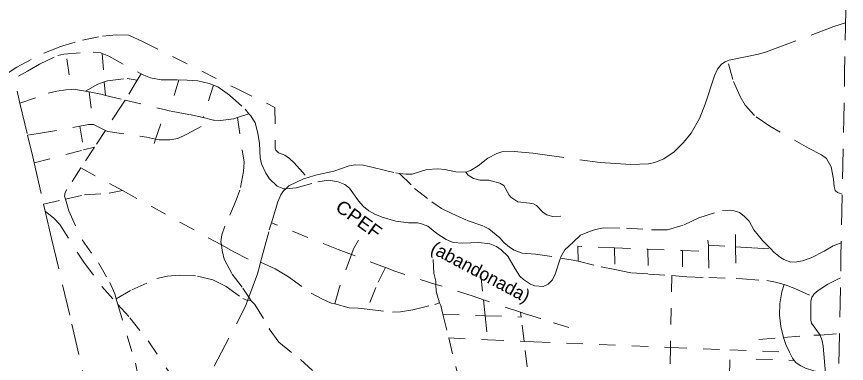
# Model space of a CAD drawing. Extents: x 783.4 to 809.8, y 7536.4 to 7564.6.
# Drawn here: x 804.65 to 809.73, y 7559.21 to 7561.34 of the extents above; entities that cross this region are included whole.
import ezdxf
from ezdxf.enums import TextEntityAlignment as Align

# ---------------------------------------------------------------- set-up
doc = ezdxf.new("R2010")
doc.units = 0
doc.header["$LTSCALE"] = 0.032
for name, pattern in [('DOTTED', [1.5, 0.3, -1.2]), ('LONG_DASHED', [7.5, 6, -1.5]), ('MEDIUM_DASHED', [4.5, 3, -1.5]), ('SHORT_DASHED', [2.7, 1.5, -1.2])]:
    doc.linetypes.add(name, pattern=pattern)
for name, color, linetype, lineweight in [('18', 7, 'DOTTED', 13), ('35', 7, 'SHORT_DASHED', 13), ('5', 7, 'LONG_DASHED', 13), ('6', 7, 'MEDIUM_DASHED', 13), ('7', 7, 'DOTTED', 13)]:
    doc.layers.add(name, color=color, linetype=linetype, lineweight=lineweight)
doc.layers.add('61', color=7, linetype='Continuous')

msp = doc.modelspace()

# ---------------------------------------------------------------- linework, layer by layer
at = {"layer": '18'}
for points in [[(804.1349, 7560.6807), (804.7152, 7561.0021), (804.7883, 7561.0454), (804.9016, 7561.0989), (804.9376, 7561.1074), (805.1165, 7561.1192), (805.1646, 7561.1145), (805.1722, 7561.1112)], [(805.1722, 7561.1112), (805.2127, 7561.0938), (805.4119, 7560.9867)], [(805.4119, 7560.9867), (805.4267, 7560.9787), (805.4678, 7560.9618), (805.5339, 7560.9496), (805.642, 7560.9489)], [(805.642, 7560.9489), (805.6923, 7560.9486), (805.7574, 7560.9439), (805.8271, 7560.9266), (805.8529, 7560.9166)], [(805.8529, 7560.9166), (805.8802, 7560.9059), (805.9524, 7560.8561), (806.0476, 7560.7706), (806.071, 7560.7421)], [(806.071, 7560.7421), (806.0822, 7560.7285), (806.1082, 7560.6871), (806.1252, 7560.6241), (806.1353, 7560.5602), (806.1403, 7560.4728), (806.1473, 7560.4362), (806.1749, 7560.3775), (806.1959, 7560.3436), (806.244, 7560.2985), (806.2851, 7560.2826), (806.2959, 7560.2834)], [(806.2959, 7560.2834), (806.3603, 7560.2882), (806.4925, 7560.3248), (806.5567, 7560.3361), (806.6163, 7560.3262), (806.6574, 7560.3093), (806.6865, 7560.2868), (806.7406, 7560.2097), (806.7717, 7560.1749), (806.8037, 7560.1486), (806.8408, 7560.127), (806.8869, 7560.1092), (806.9701, 7560.0847), (807.0468, 7560.0739), (807.1029, 7560.0739), (807.1279, 7560.0683), (807.166, 7560.0532), (807.2211, 7560.0081), (807.2783, 7559.9724), (807.3204, 7559.9545), (807.3795, 7559.9498), (807.4772, 7559.9531), (807.5444, 7559.9465), (807.5854, 7559.9296), (807.6145, 7559.9089), (807.6556, 7559.8713), (807.6997, 7559.7933), (807.7298, 7559.7482), (807.7509, 7559.7271), (807.7935, 7559.6984), (807.8216, 7559.689), (807.8717, 7559.6853), (807.9017, 7559.6994), (807.9288, 7559.7257), (807.9458, 7559.7595), (807.9777, 7559.8588)], [(807.9777, 7559.8588), (807.9799, 7559.8657), (808.0049, 7559.9099), (808.0547, 7559.9565), (808.0992, 7559.9982), (808.1543, 7560.0217), (808.1919, 7560.0334), (808.241, 7560.0438), (808.3813, 7560.041), (808.5346, 7560.0316), (808.6333, 7560.032), (808.7346, 7560.0611), (808.8248, 7560.1053), (808.9691, 7560.1495), (809.0177, 7560.1509), (809.0408, 7560.1481), (809.0728, 7560.1368), (809.1019, 7560.1152), (809.133, 7560.0842), (809.162, 7560.0325), (809.2151, 7559.9658), (809.2645, 7559.9147)], [(809.2645, 7559.9147), (809.2833, 7559.8953), (809.3254, 7559.8615), (809.3445, 7559.85), (809.3875, 7559.834), (809.4246, 7559.8359), (809.4587, 7559.8424), (809.5118, 7559.8594), (809.592, 7559.9007), (809.6461, 7559.9327), (809.6963, 7559.9524)]]:
    msp.add_lwpolyline(points, dxfattribs=at)
at = {"layer": '35'}
msp.add_lwpolyline([(809.6166, 7555.9048), (809.6222, 7556.1875), (809.6278, 7556.4702), (809.6333, 7556.7528), (809.6389, 7557.0354), (809.6445, 7557.3181), (809.65, 7557.6007), (809.6556, 7557.8834), (809.6612, 7558.166), (809.6667, 7558.4487), (809.6722, 7558.7314), (809.6778, 7559.014), (809.6834, 7559.2967), (809.6889, 7559.5793), (809.6945, 7559.862), (809.7001, 7560.1446), (809.7056, 7560.4272), (809.7112, 7560.7099), (809.7168, 7560.9926), (809.7223, 7561.2752), (809.7278, 7561.5578)], dxfattribs=at)
at = {"layer": '5'}
msp.add_line((804.8138, 7560.188), (804.8235, 7560.1454), dxfattribs=at)
for points in [[(809.0009, 7561.066), (809.0102, 7561.0695), (809.1896, 7561.1071), (809.2387, 7561.1212), (809.6501, 7561.2758), (809.7227, 7561.2979)], [(807.3992, 7560.3855), (807.4278, 7560.3948), (807.4739, 7560.423), (807.533, 7560.4699), (807.5881, 7560.4991), (807.6192, 7560.5085), (807.6943, 7560.5113), (807.8076, 7560.5), (808.22, 7560.4441), (808.4079, 7560.4305), (808.5161, 7560.4361), (808.5542, 7560.4436), (808.6103, 7560.4671), (808.673, 7560.509), (808.7311, 7560.5663), (808.7782, 7560.6236), (808.8283, 7560.7138), (808.8634, 7560.8012), (808.92, 7560.9736), (808.9391, 7561.015), (808.9641, 7561.0451), (808.9852, 7561.0601), (809.0009, 7561.066)], [(804.6518, 7560.8794), (804.669, 7560.8074), (804.7157, 7560.6118)], [(804.7157, 7560.6118), (804.7477, 7560.478), (804.7562, 7560.4409), (804.8138, 7560.188)], [(806.4272, 7560.3506), (806.4772, 7560.3671), (806.5894, 7560.3906), (806.6836, 7560.4234), (806.7217, 7560.43), (806.7718, 7560.4272), (806.9707, 7560.3797), (806.9913, 7560.3772)], [(806.9913, 7560.3772), (807.0329, 7560.3722), (807.0689, 7560.3722), (807.1601, 7560.4004), (807.2273, 7560.4051), (807.2689, 7560.4009), (807.337, 7560.3868), (807.3972, 7560.3849), (807.3992, 7560.3855)], [(806.2959, 7560.2834), (806.3141, 7560.301), (806.4045, 7560.3431), (806.4272, 7560.3506)], [(806.2084, 7560.0741), (806.248, 7560.2023), (806.266, 7560.2465), (806.283, 7560.2709), (806.2959, 7560.2834)], [(804.8235, 7560.1454), (804.8615, 7559.9788), (804.9873, 7559.4549), (805.1943, 7558.5495), (805.2861, 7558.1712), (805.3146, 7558.0338), (805.3268, 7557.9814)], [(806.142, 7559.8336), (806.1953, 7560.0317), (806.2084, 7560.0741)], [(806.0706, 7559.6187), (806.1226, 7559.7616), (806.1368, 7559.8145), (806.142, 7559.8336)], [(809.692, 7559.7376), (809.6148, 7559.6982), (809.5545, 7559.6602), (809.5307, 7559.6394), (809.5193, 7559.6232)], [(805.7227, 7558.9393), (806.0525, 7559.5689), (806.0625, 7559.5988), (806.0706, 7559.6187)], [(809.5193, 7559.6232), (809.5165, 7559.6193), (809.5093, 7559.5918), (809.5093, 7559.4794), (809.5133, 7559.4593), (809.5671, 7559.3876)], [(809.5671, 7559.3876), (809.5803, 7559.3526), (809.5858, 7559.3199), (809.6006, 7559.1539)]]:
    msp.add_lwpolyline(points, dxfattribs=at)
at = {"layer": '6'}
for points in [[(804.5916, 7560.9883), (804.649, 7561.0282), (804.8154, 7561.1128), (804.9116, 7561.1517), (805.0526, 7561.1923), (805.1748, 7561.2174), (805.2594, 7561.2247), (805.3348, 7561.224), (805.4243, 7561.1824), (805.9978, 7560.8938), (806.2298, 7560.7804), (806.2317, 7560.5304), (806.2354, 7560.5199), (806.2517, 7560.5019), (806.2902, 7560.488), (806.3183, 7560.4686), (806.3479, 7560.4409), (806.4272, 7560.3506)], [(809.7021, 7560.2496), (809.6738, 7560.2597), (809.66, 7560.2727), (809.6523, 7560.2958), (809.6492, 7560.342), (809.6344, 7560.4165), (809.6064, 7560.4685), (809.5752, 7560.4909), (809.4968, 7560.5309), (809.2584, 7560.6669), (809.1646, 7560.7323), (809.1091, 7560.7954), (809.0773, 7560.8482), (809.0329, 7560.9508), (809.0009, 7561.066)], [(806.9913, 7560.3772), (807.085, 7560.2854), (807.1912, 7560.2033), (807.2499, 7560.1627), (807.312, 7560.1308), (807.4075, 7560.0878), (807.5073, 7560.0538), (807.5381, 7560.0368), (807.6061, 7559.982), (807.6305, 7559.9542), (807.6646, 7559.9251), (807.6949, 7559.9071), (807.7422, 7559.889), (807.8251, 7559.8828), (807.9777, 7559.8588)], [(807.9777, 7559.8588), (808.0563, 7559.8464), (808.0857, 7559.8392)], [(808.0857, 7559.8392), (808.2262, 7559.8045), (808.3108, 7559.7881)], [(808.3108, 7559.7881), (808.4126, 7559.7684), (808.5158, 7559.7611), (808.6588, 7559.751), (808.7266, 7559.7462)], [(808.7266, 7559.7462), (808.7518, 7559.7444), (808.8859, 7559.7394), (809.0523, 7559.7331)], [(809.0523, 7559.7331), (809.0925, 7559.7316), (809.2401, 7559.7208), (809.2941, 7559.7104), (809.3459, 7559.6959)], [(809.3459, 7559.6959), (809.3533, 7559.6938), (809.4118, 7559.673), (809.5193, 7559.6232)]]:
    msp.add_lwpolyline(points, dxfattribs=at)
at = {"layer": '7'}
for p, q in [((804.9552, 7561.0783), (804.9821, 7560.8912)), ((805.1722, 7561.1112), (805.1855, 7560.9366)), ((805.1855, 7560.9366), (805.1918, 7560.8547)), ((805.642, 7560.9489), (805.5834, 7560.7607)), ((805.8529, 7560.9166), (805.7897, 7560.7184)), ((805.4998, 7560.5865), (805.561, 7560.7661)), ((805.7897, 7560.7184), (805.8542, 7560.7035)), ((806.0012, 7560.7189), (806.071, 7560.7421)), ((805.0356, 7560.6665), (805.0584, 7560.5207)), ((805.1924, 7560.6404), (805.1259, 7560.5385)), ((805.491, 7560.5606), (805.4998, 7560.5865)), ((805.1259, 7560.5385), (805.0424, 7560.4106)), ((805.0424, 7560.4106), (805.296, 7560.2716)), ((805.296, 7560.2716), (805.9022, 7559.9393)), ((804.8138, 7560.188), (804.9477, 7560.2186)), ((808.88, 7559.969), (808.8836, 7559.937)), ((809.0487, 7560.0037), (809.0497, 7559.9276)), ((808.3073, 7559.9219), (808.3108, 7559.7881)), ((808.8836, 7559.937), (809.0497, 7559.9276)), ((809.0497, 7559.9276), (809.0523, 7559.7331)), ((808.7237, 7559.9043), (808.8841, 7559.8976)), ((807.4898, 7559.7561), (807.5059, 7559.6035)), ((808.6588, 7559.751), (808.6507, 7559.3119)), ((806.0706, 7559.6187), (806.0844, 7559.5967)), ((807.5059, 7559.6035), (807.5163, 7559.5058)), ((806.0625, 7559.5988), (806.0844, 7559.5967)), ((807.2576, 7559.5153), (807.2935, 7559.3698)), ((807.5163, 7559.5058), (807.5318, 7559.3586)), ((807.7373, 7559.4976), (807.7338, 7559.5271)), ((807.7549, 7559.348), (807.7373, 7559.4976)), ((807.773, 7559.1938), (807.7549, 7559.348)), ((809.1915, 7559.3601), (809.3427, 7559.3733)), ((809.5671, 7559.3876), (809.6853, 7559.3967)), ((808.6507, 7559.3119), (808.6441, 7558.9564)), ((808.6507, 7559.3119), (809.0149, 7559.2974)), ((809.0149, 7559.2974), (809.3795, 7559.2829)), ((809.1753, 7559.2405), (809.4086, 7559.2319))]:
    msp.add_line(p, q, dxfattribs=at)
for points in [[(805.4119, 7560.9867), (805.3875, 7560.9474), (805.3122, 7560.8258)], [(805.0709, 7560.8806), (805.1448, 7560.9226), (805.1855, 7560.9366)], [(805.1855, 7560.9366), (805.204, 7560.9429), (805.3245, 7560.9577), (805.3875, 7560.9474)], [(804.669, 7560.8074), (804.842, 7560.8678), (804.8947, 7560.881), (804.9504, 7560.8893), (804.9821, 7560.8912)], [(804.9821, 7560.8912), (804.9971, 7560.8921), (805.0709, 7560.8806)], [(805.0709, 7560.8806), (805.0728, 7560.8803), (805.0922, 7560.8762), (805.1171, 7560.6763)], [(805.0922, 7560.8762), (805.1734, 7560.8591), (805.1918, 7560.8547), (805.3122, 7560.8258)], [(805.3122, 7560.8258), (805.2889, 7560.7882), (805.1924, 7560.6404)], [(805.3122, 7560.8258), (805.561, 7560.7661), (805.5834, 7560.7607)], [(805.5834, 7560.7607), (805.604, 7560.7558), (805.7064, 7560.7377), (805.7897, 7560.7184)], [(805.8542, 7560.7035), (805.8552, 7560.7033), (805.896, 7560.7012), (805.9791, 7560.7116), (806.0012, 7560.7189)], [(806.0012, 7560.7189), (806.0406, 7560.4457), (806.0372, 7560.3885), (806.0153, 7560.2742), (805.9935, 7560.2127), (805.9227, 7560.0536), (805.9043, 7560.0018), (805.8997, 7559.9587), (805.9022, 7559.9393)], [(805.0356, 7560.6665), (805.0895, 7560.6763), (805.1171, 7560.6763)], [(805.1171, 7560.6763), (805.1191, 7560.6763), (805.1924, 7560.6404)], [(805.4998, 7560.5865), (805.5221, 7560.5818), (805.5873, 7560.5818), (805.6347, 7560.5911), (805.69, 7560.617), (805.8542, 7560.7035)], [(804.7157, 7560.6118), (804.7951, 7560.6226), (805.0356, 7560.6665)], [(805.1924, 7560.6404), (805.206, 7560.6337), (805.4431, 7560.5985), (805.4998, 7560.5865)], [(804.7562, 7560.4409), (805.0584, 7560.5207), (805.1259, 7560.5385)], [(805.0424, 7560.4106), (804.9557, 7560.2778), (804.9466, 7560.2594), (804.9421, 7560.2371), (804.9477, 7560.2186)], [(807.98, 7560.1154), (807.9295, 7560.1133), (807.8935, 7560.1229), (807.8719, 7560.1373), (807.8303, 7560.1797), (807.8127, 7560.1901), (807.7871, 7560.1957), (807.7159, 7560.2021), (807.6743, 7560.2309), (807.6631, 7560.2437), (807.6303, 7560.3037), (807.6055, 7560.3181), (807.5383, 7560.3349), (807.4839, 7560.3365), (807.4447, 7560.3464), (807.4136, 7560.3658), (807.3992, 7560.3855)], [(804.9477, 7560.2186), (805.065, 7560.2454), (805.2158, 7560.255), (805.296, 7560.2716)], [(804.9477, 7560.2186), (804.9688, 7560.1481), (805.0493, 7559.9696), (805.1502, 7559.8305), (805.2188, 7559.7098), (805.2493, 7559.6395), (805.2584, 7559.6091), (805.2687, 7559.5748)], [(804.8235, 7560.1454), (804.8768, 7560.1019), (804.913, 7560.0643), (805.0595, 7559.8335), (805.1709, 7559.6841), (805.2687, 7559.5748)], [(806.6982, 7559.8803), (806.6171, 7559.9115), (806.2084, 7560.0741)], [(806.7413, 7559.9686), (806.7112, 7559.916), (806.6982, 7559.8803)], [(805.9022, 7559.9393), (805.9066, 7559.9047), (805.9181, 7559.8529), (805.9681, 7559.7607), (806.0337, 7559.6754), (806.0706, 7559.6187)], [(805.9022, 7559.9393), (805.9781, 7559.8977), (806.1368, 7559.8145)], [(808.3073, 7559.9219), (808.083, 7559.9313), (808.0857, 7559.8392)], [(808.3073, 7559.9219), (808.5121, 7559.9132), (808.5158, 7559.7611)], [(808.5121, 7559.9132), (808.7237, 7559.9043), (808.7266, 7559.7462)], [(808.8836, 7559.937), (808.8837, 7559.9364), (808.8841, 7559.8976), (808.8859, 7559.7394)], [(809.0497, 7559.9276), (809.1522, 7559.9218), (809.2645, 7559.9147)], [(806.6982, 7559.8803), (806.6231, 7559.6737), (806.5969, 7559.5775)], [(807.215, 7559.6977), (806.9643, 7559.778), (806.9068, 7559.8001), (806.6982, 7559.8803)], [(806.142, 7559.8336), (806.2307, 7559.7926), (806.3122, 7559.7429), (806.4508, 7559.6436), (806.516, 7559.6092), (806.5738, 7559.5836), (806.5969, 7559.5775)], [(807.1989, 7559.8494), (807.2019, 7559.767), (807.2137, 7559.717), (807.215, 7559.6977)], [(805.2584, 7559.6091), (805.3545, 7559.6646), (805.5073, 7559.7334), (805.5725, 7559.7487), (805.6438, 7559.7544), (805.7559, 7559.7487), (805.8497, 7559.7258), (805.9312, 7559.6837), (806.0334, 7559.6118), (806.0625, 7559.5988)], [(806.9068, 7559.8001), (806.8475, 7559.6793), (806.795, 7559.5449)], [(807.5059, 7559.6035), (807.4429, 7559.6246), (807.215, 7559.6977)], [(807.215, 7559.6977), (807.2177, 7559.6559), (807.2286, 7559.6106), (807.2381, 7559.5856)], [(809.3459, 7559.6959), (809.3326, 7559.651), (809.3199, 7559.5777), (809.319, 7559.5099), (809.3267, 7559.439), (809.3427, 7559.3733)], [(808.0297, 7559.4327), (807.8544, 7559.4867), (807.8551, 7559.4893), (807.7607, 7559.5181), (807.7338, 7559.5271), (807.5059, 7559.6035)], [(805.2687, 7559.5748), (805.3412, 7559.4937), (805.4532, 7559.3525), (805.6168, 7559.108), (805.6198, 7559.0965), (805.6718, 7559.0109), (805.7227, 7558.9393)], [(805.2687, 7559.5748), (805.3762, 7559.2152), (805.3859, 7559.1637), (805.3873, 7559.1025), (805.3962, 7559.0364), (805.4018, 7558.9317), (805.3966, 7558.7891), (805.4022, 7558.7449), (805.3933, 7558.6113), (805.3923, 7558.4385), (805.396, 7558.396), (805.4183, 7558.3063), (805.4405, 7558.2593)], [(806.0844, 7559.5967), (806.1065, 7559.5736), (806.1963, 7559.4303), (806.1951, 7559.4245), (806.2535, 7559.3437), (806.3871, 7559.2373), (806.5047, 7559.1293), (806.5767, 7559.0701), (806.6423, 7559.0013), (806.6967, 7558.9373), (806.7911, 7558.7996), (806.8671, 7558.6396), (806.8991, 7558.4996), (806.9239, 7558.354), (806.9607, 7558.246), (807.0055, 7558.1708), (807.0517, 7558.1104)], [(806.5969, 7559.5775), (806.6832, 7559.5547), (806.7396, 7559.5512), (806.795, 7559.5449)], [(806.795, 7559.5449), (806.9499, 7559.5273), (806.9989, 7559.5301), (807.0746, 7559.5419), (807.2088, 7559.5746), (807.2381, 7559.5856)], [(807.2381, 7559.5856), (807.2444, 7559.5689), (807.2576, 7559.5153)], [(807.2576, 7559.5153), (807.5163, 7559.5058), (807.7373, 7559.4976)], [(807.2935, 7559.3698), (807.3365, 7559.1958), (807.3777, 7559.029)], [(807.2935, 7559.3698), (807.5318, 7559.3586), (807.7549, 7559.348)], [(807.7549, 7559.348), (807.8148, 7559.3452), (808.6507, 7559.3119)], [(809.3427, 7559.3733), (809.5284, 7559.3872), (809.5671, 7559.3876)], [(809.3427, 7559.3733), (809.3428, 7559.3728), (809.3573, 7559.3298), (809.3795, 7559.2829)], [(808.6441, 7558.9564), (809.0101, 7558.9366), (809.0149, 7559.2974)], [(809.3795, 7559.2829), (809.3972, 7559.2453), (809.4086, 7559.2319)], [(809.4086, 7559.2319), (809.4202, 7559.2182), (809.4491, 7559.1983), (809.478, 7559.1839), (809.529, 7559.1688), (809.6006, 7559.1539)]]:
    msp.add_lwpolyline(points, dxfattribs=at)

# ---------------------------------------------------------------- texts
at = {"layer": '61', "width": 1.1}
msp.add_text('CPEF', height=0.08, rotation=324, dxfattribs=at).set_placement((806.7201, 7560.064), align=Align.CENTER)
at = {"layer": '61'}
msp.add_text('(abandonada)', height=0.08, rotation=332, dxfattribs=at).set_placement((807.4698, 7559.7387), align=Align.CENTER)

doc.saveas('drawing.dxf')
